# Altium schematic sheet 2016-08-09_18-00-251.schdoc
size 414 x 152 mm; SheetNumber: 1; SheetTotal: 1
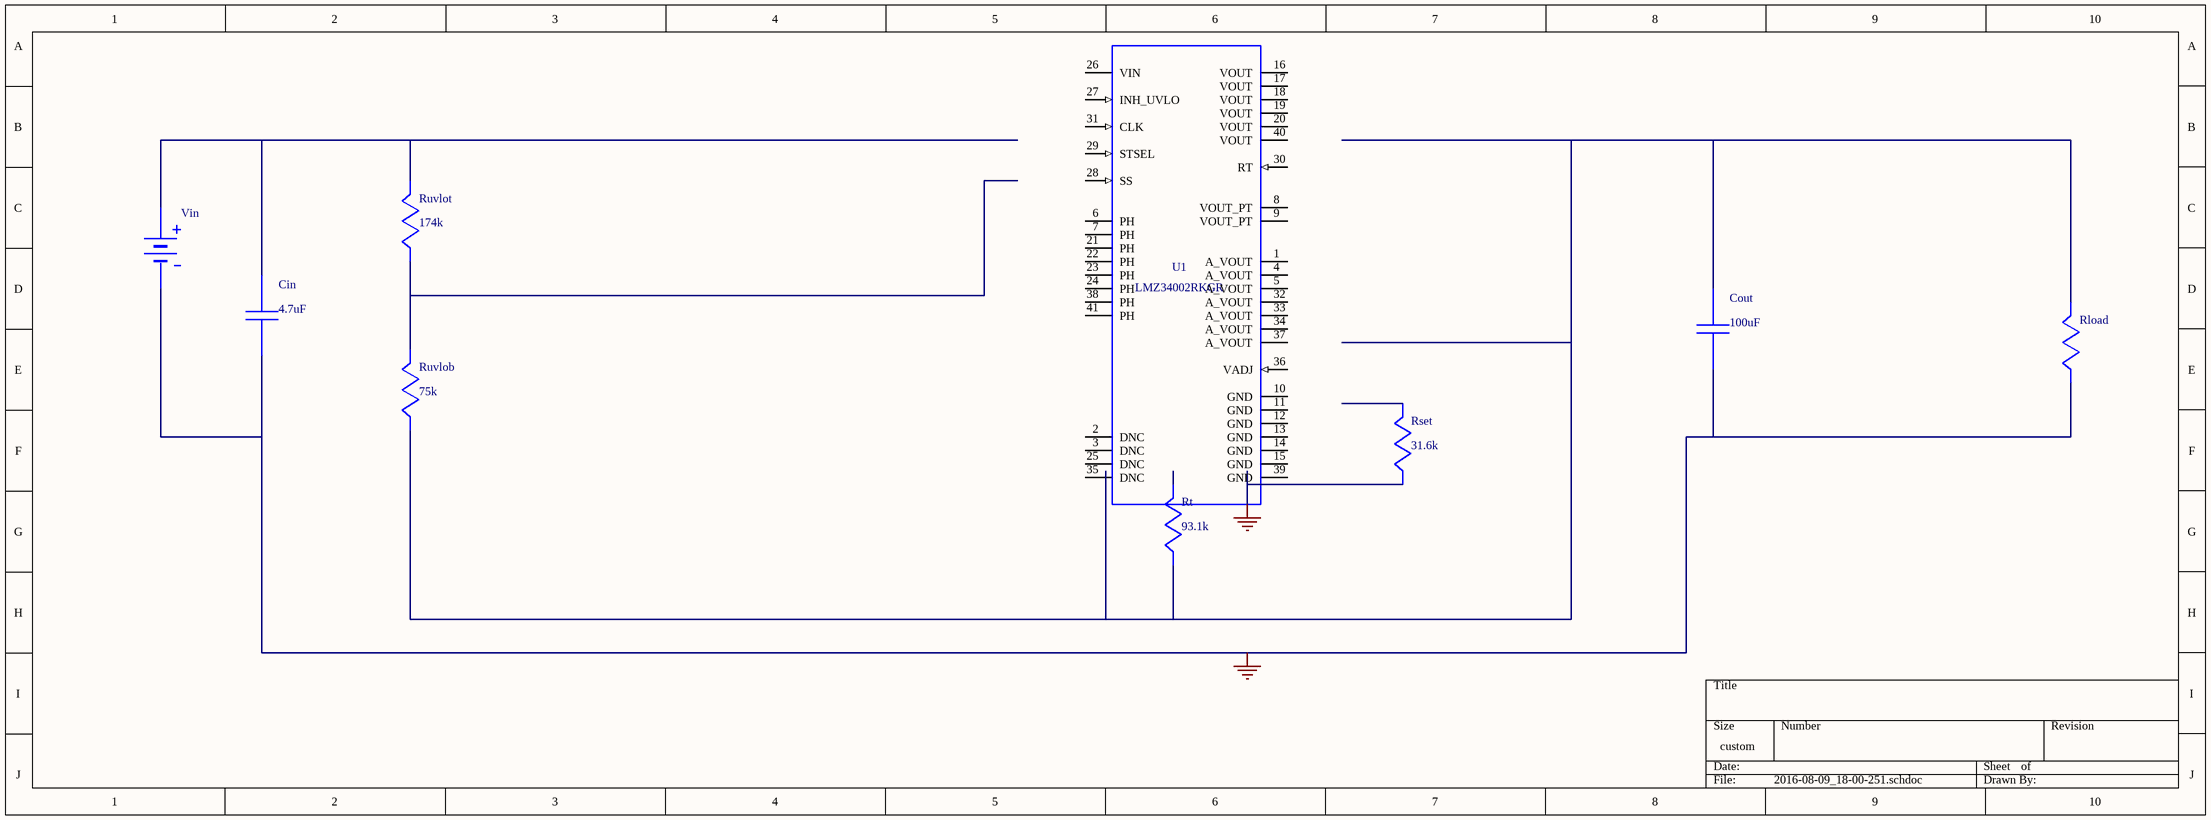
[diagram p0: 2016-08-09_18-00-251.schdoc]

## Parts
Cin  value 4.7uF  (hidden comment: GRM31CR71H475KA12L)
Cout  value 100uF  (hidden comment: GRM31CD80G107ME39L)
Rload  WB_LOAD_RESISTOR  (value not drawn)
Rset  value 31.6k  (hidden comment: CRCW040231K6FKED)
Rt  value 93.1k  (hidden comment: CRCW040293K1FKED)
Ruvlob  value 75k  (hidden comment: CRCW040275K0FKED)
Ruvlot  value 174k  (hidden comment: CRCW0402174KFKED)
U1  LMZ34002RKGR
Vin  WB_BATTERY  (value not drawn)

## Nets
0: Cin.2 Cout.1 Rload.2 Rset.2 Vin.2(-)
NetCin_1: Cin.1 Ruvlot.1 Vin.1(+)
NetCout_2: Cout.2 Rload.1 Rt.2 Ruvlob.2
NetRuvlob_1: Ruvlob.1 Ruvlot.2

Not connected (* = marked no-connect by the designer): Rset 1; Rt 1; U1 1(A_VOUT) 2(DNC) 3(DNC) 4(A_VOUT) 5(A_VOUT) 6(PH) 7(PH) 8(VOUT_PT) 9(VOUT_PT) 10(GND) 11(GND) 12(GND) 13(GND) 14(GND) 15(GND) 16(VOUT) 17(VOUT) 18(VOUT) 19(VOUT) 20(VOUT) 21(PH) 22(PH) 23(PH) 24(PH) 25(DNC) 26(VIN) 27(INH_UVLO) 28(SS) 29(STSEL) 30(RT) 31(CLK) 32(A_VOUT) 33(A_VOUT) 34(A_VOUT) 35(DNC) 36(VADJ) 37(A_VOUT) 38(PH) 39(GND) 40(VOUT) 41(PH)

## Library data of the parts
Cin = GRM31CR71H475KA12L: GRM31CR71H475KA1; Manufacturer Name: MuRata
Cout = GRM31CD80G107ME39L: GRM31CD80G107ME3; Manufacturer Name: MuRata
Rset = CRCW040231K6FKED: Manufacturer Name: Vishay-Dale
Rt = CRCW040293K1FKED: Manufacturer Name: Vishay-Dale
Ruvlob = CRCW040275K0FKED: Manufacturer Name: Vishay-Dale
Ruvlot = CRCW0402174KFKED: Manufacturer Name: Vishay-Dale
U1 = LMZ34002RKGR: Manufacturer Name: Texas Instruments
